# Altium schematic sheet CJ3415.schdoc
size 127 x 101 mm
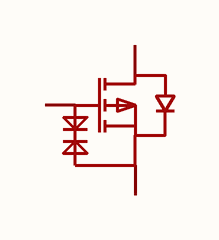
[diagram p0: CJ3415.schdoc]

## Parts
Q?  cj3415 r15  [SOT-23-3_L2.9-W1.3-P1.90-LS2.4-BR]  (value not drawn)

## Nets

Not connected (* = marked no-connect by the designer): Q? 1(G) 2(S) 3(D)

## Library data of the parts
Q? = cj3415 r15: 数量:1个P沟道;漏源电压(Vdss):20V;连续漏极电流(Id):4A;导通电阻(RDS(on)):50mΩ@4.5V;耗散功率(Pd):350mW;阈值电压(Vgs(th)):1V;; Manufacturer: CJ(江苏长电/长晶); AddInBom: yes; ModelId: c62791f0466c4ae2a892c056b845b0ca; ModelName: SOT-23-3P_L2.9-W1.3-H1.0-LS2.4-P0.95; ModelTransform: 98.425,114.173,0,180,0,0,0.0005,-0.0005,0; Number: 1个P沟道; Drain to Source Voltage: 20V; Current - Continuous Drain(Id): 4A; Pd - Power Dissipation: 350mW; Gate Threshold Voltage (Vgs(th)): 1V; Gate Charge(Qg): 17.2nC@4.5V; Input Capacitance(Ciss): 1.45nF; Reverse Transfer Capacitance (Crss@Vds): 160pF; Type: P沟道; Output Capacitance(Coss): 205pF; Vgs: ±8V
